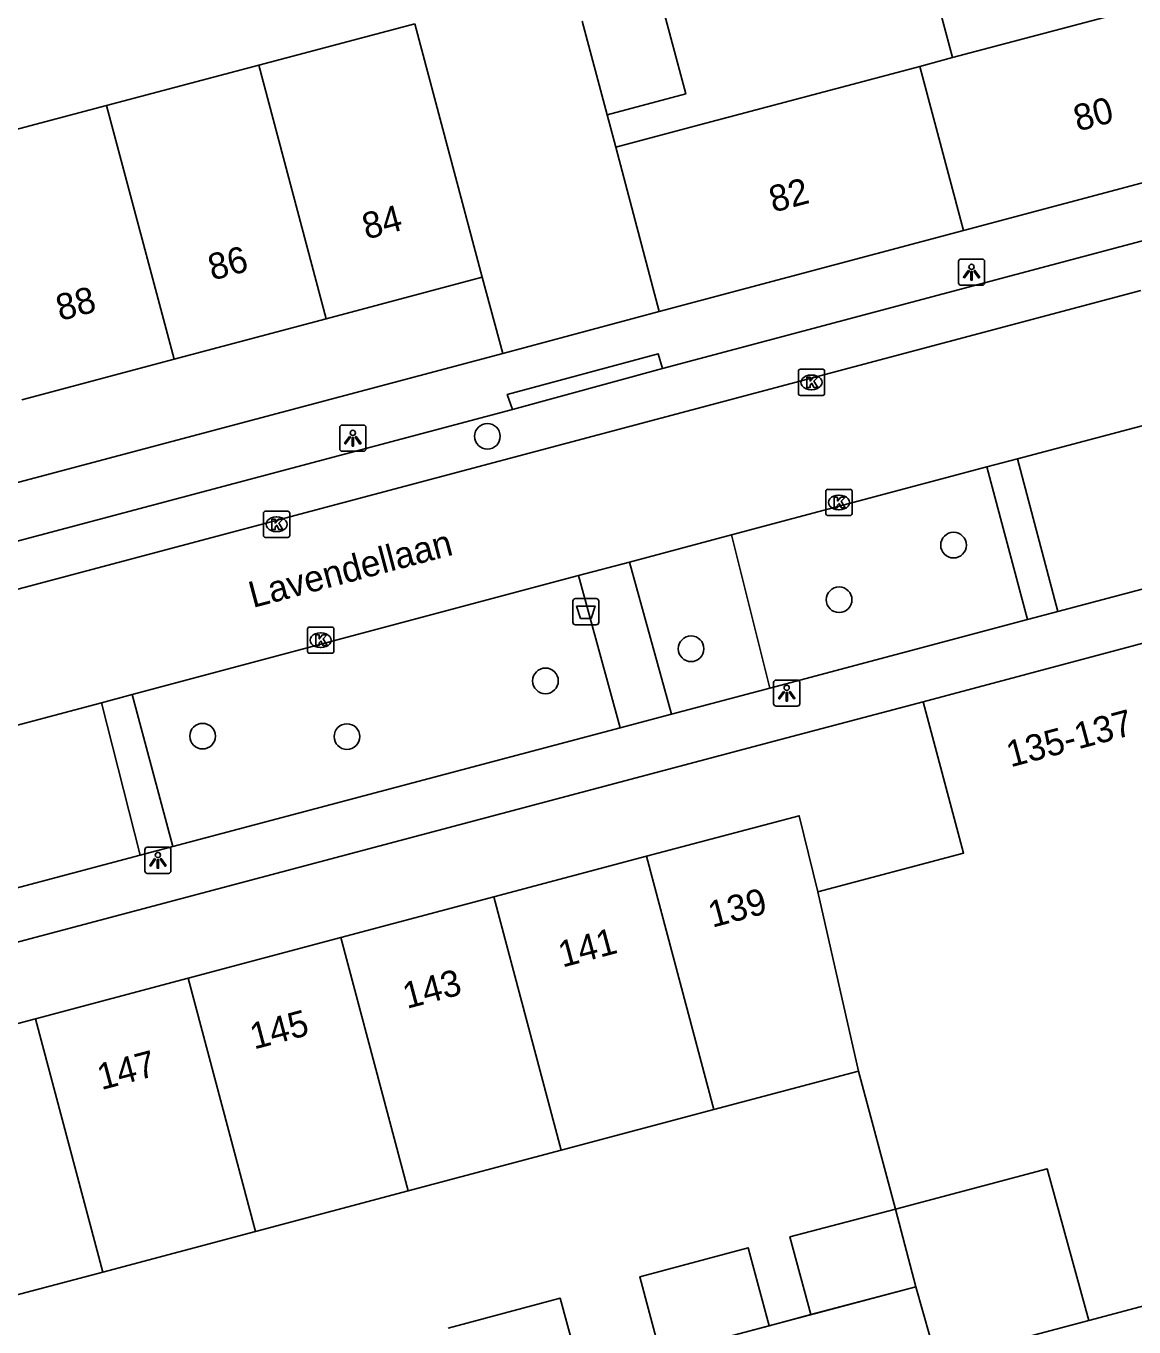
# Model space of a CAD drawing. Extents: x 162542 to 163144, y 380786 to 381511.
# Drawn here: x 162731.68 to 162773.94, y 381096.34 to 381145.96 of the extents above; entities that cross this region are included whole.
import ezdxf

# ---------------------------------------------------------------- set-up
doc = ezdxf.new("R2010")
doc.units = 0
for name, color, linetype in [('IMGEO_Afvalbak', 7, 'Continuous'), ('IMGEO_Boom', 7, 'Continuous'), ('IMGEO_Groenvoorziening', 7, 'Continuous'), ('IMGEO_Kolk', 7, 'Continuous'), ('IMGEO_Lichtpunt', 7, 'Continuous'), ('IMGEO_Muur', 7, 'Continuous'), ('IMGEO_Openbare_ruimte_label', 7, 'Continuous'), ('IMGEO_Pand', 7, 'Continuous'), ('IMGEO_Pand_nummerreeks', 7, 'Continuous'), ('IMGEO_Rijbaan_lokaal_open', 7, 'Continuous'), ('IMGEO_Voetpad_open', 7, 'Continuous')]:
    doc.layers.add(name, color=color, linetype=linetype)

msp = doc.modelspace()

# ---------------------------------------------------------------- linework, layer by layer
at = {"layer": 'IMGEO_Afvalbak'}
for p, q in [((162752.539, 381123.224), (162752.539, 381124.024)), ((162752.539, 381124.024), (162752.539, 381123.224)), ((162752.639, 381124.124), (162753.429, 381124.124)), ((162753.429, 381124.124), (162752.639, 381124.124)), ((162753.529, 381124.024), (162753.529, 381123.224)), ((162753.529, 381123.224), (162753.529, 381124.024)), ((162753.429, 381123.124), (162752.639, 381123.124)), ((162752.639, 381123.124), (162753.429, 381123.124))]:
    msp.add_line(p, q, dxfattribs=at)
msp.add_lwpolyline([(162752.682, 381123.838), (162753.386, 381123.838), (162753.237, 381123.368), (162752.831, 381123.368), (162752.682, 381123.838)], dxfattribs=at)
for centre, start, end in [((162752.639, 381124.024), 90, 180), ((162752.639, 381124.024), 90, 180), ((162753.429, 381124.024), 0, 90), ((162753.429, 381124.024), 360, 90), ((162752.639, 381123.224), 180, 270), ((162752.639, 381123.224), 180, 270), ((162753.429, 381123.224), 270, 0), ((162753.429, 381123.224), 270, 0)]:
    msp.add_arc(centre, 0.1, start, end, dxfattribs=at)
at = {"layer": 'IMGEO_Boom'}
for centre in [(162749.28, 381130.314), (162767.056, 381126.163), (162762.693, 381124.08), (162757.047, 381122.209), (162751.494, 381120.985), (162738.419, 381118.876), (162743.923, 381118.86)]:
    msp.add_circle(centre, 0.489, dxfattribs=at)
at = {"layer": 'IMGEO_Groenvoorziening'}
msp.add_lwpolyline([(162760.047, 381120.71), (162758.591, 381126.553)], dxfattribs=at)
at = {"layer": 'IMGEO_Kolk'}
for p, q in [((162761.139, 381131.946), (162761.139, 381132.798)), ((162761.214, 381132.872), (162762.066, 381132.872)), ((162762.14, 381132.798), (162762.14, 381131.946)), ((162761.627, 381132.652), (162761.652, 381132.652)), ((162762.066, 381131.872), (162761.214, 381131.872)), ((162761.65, 381132.092), (162761.625, 381132.092)), ((162762.185, 381127.365), (162762.185, 381128.217)), ((162762.26, 381128.291), (162763.112, 381128.291)), ((162762.673, 381128.071), (162762.698, 381128.071)), ((162763.186, 381128.217), (162763.186, 381127.365)), ((162740.738, 381126.531), (162740.738, 381127.383)), ((162740.813, 381127.457), (162741.665, 381127.457)), ((162741.739, 381127.383), (162741.739, 381126.531)), ((162762.696, 381127.511), (162762.671, 381127.511)), ((162741.226, 381127.237), (162741.251, 381127.237)), ((162763.112, 381127.291), (162762.26, 381127.291)), ((162741.665, 381126.457), (162740.813, 381126.457)), ((162741.249, 381126.677), (162741.224, 381126.677)), ((162742.422, 381122.111), (162742.422, 381122.963)), ((162742.497, 381123.037), (162743.349, 381123.037)), ((162743.423, 381122.963), (162743.423, 381122.111)), ((162742.91, 381122.817), (162742.935, 381122.817)), ((162743.349, 381122.037), (162742.497, 381122.037)), ((162742.933, 381122.257), (162742.908, 381122.257))]:
    msp.add_line(p, q, dxfattribs=at)
for points in [[(162761.139, 381131.946), (162761.139, 381132.798)], [(162761.214, 381132.872), (162762.066, 381132.872)], [(162762.14, 381132.798), (162762.14, 381131.946)], [(162761.46, 381132.572), (162761.583, 381132.572), (162761.583, 381132.421), (162761.713, 381132.572), (162761.877, 381132.572), (162761.731, 381132.421), (162761.884, 381132.172), (162761.732, 381132.172), (162761.647, 381132.336), (162761.583, 381132.269), (162761.583, 381132.172), (162761.46, 381132.172), (162761.46, 381132.572)], [(162762.066, 381131.872), (162761.214, 381131.872)], [(162762.185, 381127.365), (162762.185, 381128.217)], [(162762.26, 381128.291), (162763.112, 381128.291)], [(162762.506, 381127.991), (162762.629, 381127.991), (162762.629, 381127.84), (162762.759, 381127.991), (162762.923, 381127.991), (162762.777, 381127.84), (162762.93, 381127.591), (162762.778, 381127.591), (162762.693, 381127.755), (162762.629, 381127.688), (162762.629, 381127.591), (162762.506, 381127.591), (162762.506, 381127.991)], [(162763.186, 381128.217), (162763.186, 381127.365)], [(162740.738, 381126.531), (162740.738, 381127.383)], [(162740.813, 381127.457), (162741.665, 381127.457)], [(162741.739, 381127.383), (162741.739, 381126.531)], [(162741.059, 381127.157), (162741.182, 381127.157), (162741.182, 381127.006), (162741.312, 381127.157), (162741.476, 381127.157), (162741.33, 381127.006), (162741.483, 381126.757), (162741.331, 381126.757), (162741.246, 381126.921), (162741.182, 381126.854), (162741.182, 381126.757), (162741.059, 381126.757), (162741.059, 381127.157)], [(162763.112, 381127.291), (162762.26, 381127.291)], [(162741.665, 381126.457), (162740.813, 381126.457)], [(162742.422, 381122.111), (162742.422, 381122.963)], [(162742.497, 381123.037), (162743.349, 381123.037)], [(162743.423, 381122.963), (162743.423, 381122.111)], [(162742.743, 381122.737), (162742.866, 381122.737), (162742.866, 381122.586), (162742.996, 381122.737), (162743.16, 381122.737), (162743.014, 381122.586), (162743.167, 381122.337), (162743.015, 381122.337), (162742.93, 381122.501), (162742.866, 381122.434), (162742.866, 381122.337), (162742.743, 381122.337), (162742.743, 381122.737)], [(162743.349, 381122.037), (162742.497, 381122.037)]]:
    msp.add_lwpolyline(points, dxfattribs=at)
for centre, start, end in [((162761.216, 381132.796), 91.552, 178.448), ((162761.216, 381132.796), 91.552, 178.448), ((162762.064, 381132.796), 1.552, 88.448), ((162762.064, 381132.796), 1.552, 88.448), ((162761.216, 381131.948), 181.552, 268.448), ((162761.216, 381131.948), 181.552, 268.448), ((162762.064, 381131.948), 271.552, 358.448), ((162762.064, 381131.948), 271.552, 358.448), ((162762.262, 381128.215), 91.552, 178.448), ((162762.262, 381128.215), 91.552, 178.448), ((162763.11, 381128.215), 1.552, 88.448), ((162763.11, 381128.215), 1.552, 88.448), ((162740.815, 381127.381), 91.552, 178.448), ((162740.815, 381127.381), 91.552, 178.448), ((162741.663, 381127.381), 1.552, 88.448), ((162741.663, 381127.381), 1.552, 88.448), ((162762.262, 381127.367), 181.552, 268.448), ((162762.262, 381127.367), 181.552, 268.448), ((162763.11, 381127.367), 271.552, 358.448), ((162763.11, 381127.367), 271.552, 358.448), ((162740.815, 381126.533), 181.552, 268.448), ((162740.815, 381126.533), 181.552, 268.448), ((162741.663, 381126.533), 271.552, 358.448), ((162741.663, 381126.533), 271.552, 358.448), ((162742.499, 381122.961), 91.552, 178.448), ((162742.499, 381122.961), 91.552, 178.448), ((162743.347, 381122.961), 1.552, 88.448), ((162743.347, 381122.961), 1.552, 88.448), ((162742.499, 381122.113), 181.552, 268.448), ((162742.499, 381122.113), 181.552, 268.448), ((162743.347, 381122.113), 271.552, 358.448), ((162743.347, 381122.113), 271.552, 358.448)]:
    msp.add_arc(centre, 0.0765, start, end, dxfattribs=at)
for centre, major_axis, ratio, start_param, end_param in [((162761.626, 381132.372), (-0.387, 0.002), 0.722429, 4.712389, 7.853982), ((162761.651, 381132.372), (-0.39, 0.002), 0.717154, 1.570796, 4.712389), ((162762.672, 381127.791), (-0.387, 0.002), 0.722429, 4.712389, 7.853982), ((162762.697, 381127.791), (-0.39, 0.002), 0.717154, 1.570796, 4.712389), ((162741.225, 381126.957), (-0.387, 0.002), 0.722429, 4.712389, 7.853982), ((162741.25, 381126.957), (-0.39, 0.002), 0.717154, 1.570796, 4.712389), ((162742.909, 381122.537), (-0.387, 0.002), 0.722429, 4.712389, 7.853982), ((162742.934, 381122.537), (-0.39, 0.002), 0.717154, 1.570796, 4.712389)]:
    msp.add_ellipse(centre, major_axis=major_axis, ratio=ratio, start_param=start_param, end_param=end_param, dxfattribs=at)
at = {"layer": 'IMGEO_Lichtpunt'}
for p, q in [((162767.246, 381136.979), (162767.246, 381136.172)), ((162767.246, 381136.979), (162767.246, 381136.172)), ((162768.148, 381137.074), (162767.34, 381137.074)), ((162768.148, 381137.074), (162767.34, 381137.074)), ((162768.242, 381136.172), (162768.242, 381136.979)), ((162768.242, 381136.172), (162768.242, 381136.979)), ((162767.34, 381136.078), (162768.148, 381136.078)), ((162767.34, 381136.078), (162768.148, 381136.078)), ((162743.649, 381130.647), (162743.649, 381129.84)), ((162743.649, 381130.647), (162743.649, 381129.84)), ((162744.551, 381130.742), (162743.743, 381130.742)), ((162744.551, 381130.742), (162743.743, 381130.742)), ((162744.645, 381129.84), (162744.645, 381130.647)), ((162744.645, 381129.84), (162744.645, 381130.647)), ((162743.743, 381129.746), (162744.551, 381129.746)), ((162743.743, 381129.746), (162744.551, 381129.746)), ((162760.196, 381120.922), (162760.196, 381120.115)), ((162760.196, 381120.922), (162760.196, 381120.115)), ((162761.098, 381121.017), (162760.29, 381121.017)), ((162761.098, 381121.017), (162760.29, 381121.017)), ((162761.192, 381120.115), (162761.192, 381120.922)), ((162761.192, 381120.115), (162761.192, 381120.922)), ((162760.29, 381120.021), (162761.098, 381120.021)), ((162760.29, 381120.021), (162761.098, 381120.021)), ((162736.215, 381114.544), (162736.215, 381113.737)), ((162736.215, 381114.544), (162736.215, 381113.737)), ((162737.117, 381114.639), (162736.309, 381114.639)), ((162737.117, 381114.639), (162736.309, 381114.639)), ((162737.211, 381113.737), (162737.211, 381114.544)), ((162737.211, 381113.737), (162737.211, 381114.544)), ((162736.309, 381113.643), (162737.117, 381113.643)), ((162736.309, 381113.643), (162737.117, 381113.643))]:
    msp.add_line(p, q, dxfattribs=at)
for points in [[(162767.62, 381136.643), (162767.659, 381136.615), (162767.471, 381136.353), (162767.433, 381136.38), (162767.62, 381136.643)], [(162767.722, 381136.595), (162767.769, 381136.595), (162767.769, 381136.273), (162767.722, 381136.273), (162767.722, 381136.595)], [(162767.832, 381136.615), (162767.87, 381136.642), (162768.057, 381136.38), (162768.018, 381136.352), (162767.832, 381136.615)], [(162744.023, 381130.311), (162744.062, 381130.283), (162743.874, 381130.021), (162743.836, 381130.048), (162744.023, 381130.311)], [(162744.235, 381130.283), (162744.273, 381130.31), (162744.46, 381130.048), (162744.421, 381130.02), (162744.235, 381130.283)], [(162744.125, 381130.263), (162744.172, 381130.263), (162744.172, 381129.941), (162744.125, 381129.941), (162744.125, 381130.263)], [(162760.57, 381120.586), (162760.609, 381120.558), (162760.421, 381120.296), (162760.383, 381120.323), (162760.57, 381120.586)], [(162760.672, 381120.538), (162760.719, 381120.538), (162760.719, 381120.216), (162760.672, 381120.216), (162760.672, 381120.538)], [(162760.782, 381120.558), (162760.82, 381120.585), (162761.007, 381120.323), (162760.968, 381120.295), (162760.782, 381120.558)], [(162736.589, 381114.208), (162736.628, 381114.18), (162736.44, 381113.918), (162736.402, 381113.945), (162736.589, 381114.208)], [(162736.691, 381114.16), (162736.738, 381114.16), (162736.738, 381113.838), (162736.691, 381113.838), (162736.691, 381114.16)], [(162736.801, 381114.18), (162736.839, 381114.207), (162737.026, 381113.945), (162736.987, 381113.917), (162736.801, 381114.18)]]:
    msp.add_lwpolyline(points, dxfattribs=at)
for centre in [(162767.745, 381136.777), (162744.148, 381130.445), (162760.695, 381120.72), (162736.714, 381114.342)]:
    msp.add_circle(centre, 0.0994, dxfattribs=at)
for centre, start, end in [((162767.34, 381136.979), 90, 180), ((162767.34, 381136.979), 90, 180), ((162768.148, 381136.979), 0, 90), ((162768.148, 381136.979), 0, 90), ((162767.34, 381136.172), 180, 270), ((162767.34, 381136.172), 180, 270), ((162768.148, 381136.172), 270, 0), ((162768.148, 381136.172), 270, 360), ((162743.743, 381130.647), 90, 180), ((162743.743, 381130.647), 90, 180), ((162744.551, 381130.647), 0, 90), ((162744.551, 381130.647), 0, 90), ((162743.743, 381129.84), 180, 270), ((162743.743, 381129.84), 180, 270), ((162744.551, 381129.84), 270, 0), ((162744.551, 381129.84), 270, 360), ((162760.29, 381120.922), 90, 180), ((162760.29, 381120.922), 90, 180), ((162761.098, 381120.922), 0, 90), ((162761.098, 381120.922), 0, 90), ((162760.29, 381120.115), 180, 270), ((162760.29, 381120.115), 180, 270), ((162761.098, 381120.115), 270, 0), ((162761.098, 381120.115), 270, 360), ((162736.309, 381114.544), 90, 180), ((162736.309, 381114.544), 90, 180), ((162737.117, 381114.544), 0, 90), ((162737.117, 381114.544), 0, 90), ((162736.309, 381113.737), 180, 270), ((162736.309, 381113.737), 180, 270), ((162737.117, 381113.737), 270, 0), ((162737.117, 381113.737), 270, 360)]:
    msp.add_arc(centre, 0.0946, start, end, dxfattribs=at)
at = {"layer": 'IMGEO_Muur'}
for points in [[(162760.455, 381118.748), (162765.901, 381120.189)], [(162772.214, 381096.585), (162766.422, 381095.044), (162765.622, 381097.877), (162701.846, 381080.936)]]:
    msp.add_lwpolyline(points, dxfattribs=at)
at = {"layer": 'IMGEO_Pand'}
for points in [[(162765.752, 381149.544), (162767.017, 381144.759)], [(162777.372, 381147.511), (162767.017, 381144.759)], [(162755.897, 381146.939), (162756.846, 381143.372), (162753.846, 381142.574)], [(162740.558, 381144.471), (162746.516, 381146.053)], [(162746.516, 381146.053), (162749.085, 381136.384)], [(162753.846, 381142.574), (162752.9, 381146.147)], [(162767.017, 381144.759), (162765.765, 381144.426)], [(162734.754, 381142.93), (162740.558, 381144.471)], [(162740.558, 381144.471), (162743.131, 381134.8)], [(162765.765, 381144.426), (162757.174, 381142.139), (162754.172, 381141.34)], [(162765.765, 381144.426), (162767.431, 381138.168)], [(162728.95, 381141.388), (162734.754, 381142.93)], [(162737.328, 381133.255), (162734.754, 381142.93)], [(162755.829, 381135.079), (162754.172, 381141.34)], [(162767.431, 381138.168), (162779.034, 381141.256)], [(162755.829, 381135.079), (162767.431, 381138.168)], [(162743.131, 381134.8), (162749.085, 381136.384)], [(162743.131, 381134.8), (162737.328, 381133.255)], [(162731.525, 381131.711), (162737.328, 381133.255)], [(162765.901, 381120.189), (162777.951, 381123.405)], [(162761.884, 381112.936), (162767.441, 381114.419), (162765.901, 381120.189)], [(162761.884, 381112.936), (162761.17, 381115.842), (162755.344, 381114.293)], [(162749.519, 381112.744), (162755.344, 381114.293)], [(162755.344, 381114.293), (162757.913, 381104.631)], [(162763.436, 381106.099), (162761.884, 381112.936)], [(162749.519, 381112.744), (162743.693, 381111.195)], [(162752.088, 381103.082), (162749.519, 381112.744)], [(162743.693, 381111.195), (162737.868, 381109.646)], [(162746.262, 381101.533), (162743.693, 381111.195)], [(162737.868, 381109.646), (162732.042, 381108.097)], [(162737.868, 381109.646), (162740.436, 381099.985)], [(162732.042, 381108.097), (162726.216, 381106.548)], [(162734.611, 381098.436), (162732.042, 381108.097)], [(162763.436, 381106.099), (162757.913, 381104.631)], [(162764.843, 381100.832), (162763.436, 381106.099)], [(162757.913, 381104.631), (162752.088, 381103.082)], [(162752.088, 381103.082), (162746.262, 381101.533)], [(162772.214, 381096.585), (162770.633, 381102.367), (162764.843, 381100.832)], [(162746.262, 381101.533), (162740.436, 381099.985)], [(162764.843, 381100.832), (162760.816, 381099.779), (162761.612, 381096.812)], [(162765.622, 381097.877), (162764.843, 381100.832)], [(162740.436, 381099.985), (162734.611, 381098.436)], [(162784.24, 381099.787), (162772.214, 381096.585)], [(162760.023, 381096.39), (162759.227, 381099.362), (162755.09, 381098.253), (162755.884, 381095.29)], [(162734.611, 381098.436), (162728.785, 381096.887)], [(162761.612, 381096.812), (162765.622, 381097.877)], [(162752.851, 381094.485), (162752.06, 381097.438), (162747.779, 381096.29)], [(162755.884, 381095.29), (162760.023, 381096.39)]]:
    msp.add_lwpolyline(points, dxfattribs=at)
at = {"layer": 'IMGEO_Rijbaan_lokaal_open'}
for points in [[(162754.172, 381141.34), (162753.846, 381142.574)], [(162749.085, 381136.384), (162749.869, 381133.472)], [(162774.201, 381135.871), (162666.934, 381107.34)], [(162749.869, 381133.472), (162755.829, 381135.079)], [(162769.49, 381129.452), (162775.451, 381131.037)], [(162768.331, 381129.144), (162769.49, 381129.452)], [(162758.591, 381126.553), (162768.331, 381129.144)], [(162754.693, 381125.516), (162758.591, 381126.553)], [(162752.751, 381124.999), (162754.693, 381125.516)], [(162735.727, 381120.464), (162752.751, 381124.999)], [(162734.561, 381120.153), (162735.727, 381120.464)], [(162724.071, 381117.358), (162734.561, 381120.153)]]:
    msp.add_lwpolyline(points, dxfattribs=at)
at = {"layer": 'IMGEO_Voetpad_open'}
for points in [[(162755.957, 381132.897), (162781.519, 381139.707)], [(162680.279, 381114.986), (162685.734, 381116.428), (162749.869, 381133.472)], [(162750.234, 381131.33), (162750.039, 381131.907), (162755.797, 381133.463), (162755.957, 381132.897)], [(162755.957, 381132.897), (162750.234, 381131.33)], [(162666.934, 381107.34), (162666.499, 381109.073), (162750.234, 381131.33)], [(162782.046, 381131.197), (162783.201, 381126.857), (162782.697, 381126.723), (162771.037, 381123.628)], [(162769.49, 381129.452), (162771.037, 381123.628)], [(162769.877, 381123.32), (162768.331, 381129.144)], [(162754.693, 381125.516), (162756.301, 381119.715)], [(162752.751, 381124.999), (162754.347, 381119.196)], [(162771.037, 381123.628), (162769.877, 381123.32)], [(162769.877, 381123.32), (162760.047, 381120.71)], [(162737.289, 381114.667), (162735.727, 381120.464)], [(162760.047, 381120.71), (162756.301, 381119.715)], [(162696.302, 381101.71), (162760.455, 381118.748), (162765.901, 381120.189)], [(162734.561, 381120.153), (162736.038, 381114.335)], [(162756.301, 381119.715), (162754.347, 381119.196)], [(162754.347, 381119.196), (162737.289, 381114.667)], [(162737.289, 381114.667), (162736.038, 381114.335)], [(162736.038, 381114.335), (162725.703, 381111.591)], [(162765.622, 381097.877), (162766.422, 381095.044), (162772.214, 381096.585)], [(162760.023, 381096.39), (162761.612, 381096.812)]]:
    msp.add_lwpolyline(points, dxfattribs=at)

# ---------------------------------------------------------------- texts
at = {"layer": 'IMGEO_Openbare_ruimte_label'}
msp.add_text('Lavendellaan', height=1, rotation=14.8835, dxfattribs=at).set_placement((162740.334, 381123.762))
at = {"layer": 'IMGEO_Pand_nummerreeks'}
for s, rotation, p in [('80', 14.9064, (162771.792, 381141.936)), ('82', 14.9064, (162760.18, 381138.845)), ('84', 14.9015, (162744.664, 381137.815)), ('86', 14.9015, (162738.786, 381136.251)), ('88', 14.9015, (162732.986, 381134.708)), ('135-137', 14.9435, (162769.229, 381117.683)), ('139', 14.8893, (162757.856, 381111.567)), ('141', 14.8893, (162752.14, 381110.047)), ('143', 14.8893, (162746.208, 381108.47)), ('145', 14.8893, (162740.382, 381106.921)), ('147', 14.8893, (162734.557, 381105.372))]:
    msp.add_text(s, height=1, rotation=rotation, dxfattribs=at).set_placement(p)

doc.saveas('drawing.dxf')
